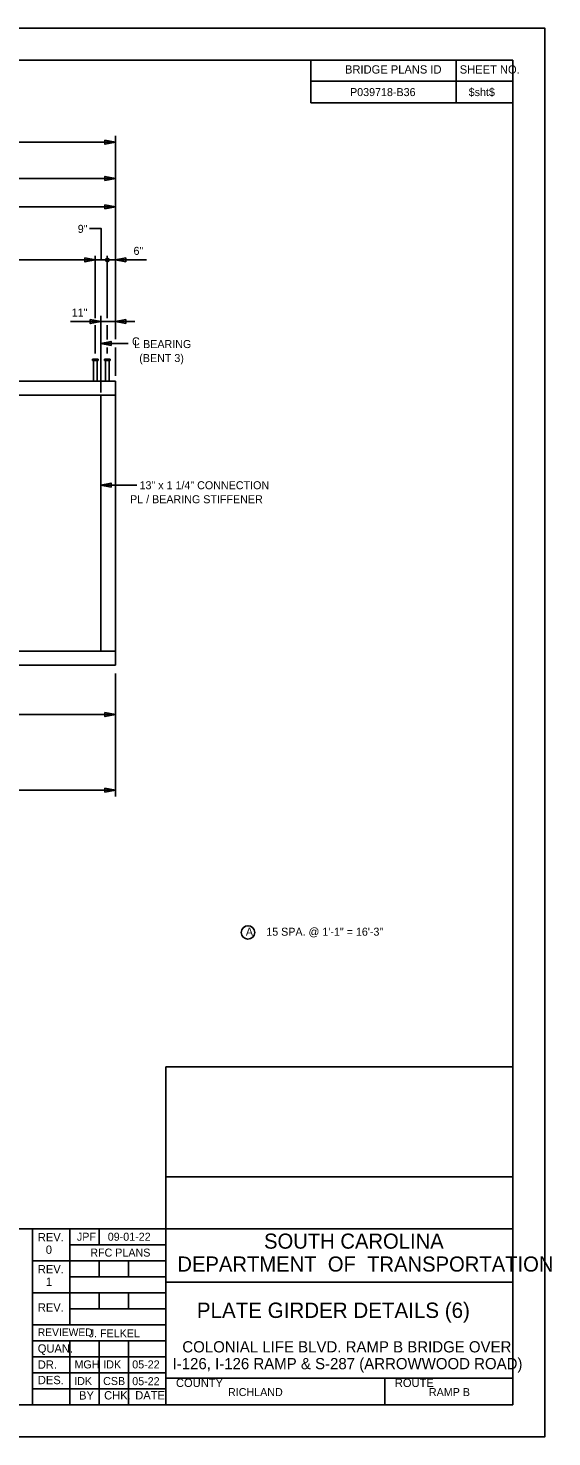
# Model space of a CAD drawing. Extents: x -305 to -161, y -187 to -99.
# Drawn here: x -193.4 to -160.8, y -187.5 to -99.5 of the extents above; entities that cross this region are included whole.
import ezdxf

# ---------------------------------------------------------------- set-up
doc = ezdxf.new("R2010")
doc.units = 0
for name, color, linetype in [('BR_AUTO DIMENSION', 7, 'Continuous'), ('BR_BORDER LINES', 7, 'Continuous'), ('BR_CENTER LINES', 7, 'Continuous'), ('BR_STRUCTURAL STEEL', 7, 'Continuous'), ('BR_TEXT', 7, 'Continuous'), ('Default', 7, 'Continuous'), ('Level 31', 7, 'Continuous')]:
    doc.layers.add(name, color=color, linetype=linetype)

msp = doc.modelspace()

# ---------------------------------------------------------------- linework, layer by layer
at = {"layer": 'BR_AUTO DIMENSION'}
for p, q in [((-188.002, -118.927), (-188.002, -106.206)), ((-284.433, -106.618), (-188.002, -106.618)), ((-226.782, -108.876), (-188.002, -108.876)), ((-188.002, -110.653), (-206.782, -110.653)), ((-219.002, -113.971), (-189.252, -113.971)), ((-189.252, -117.609), (-189.252, -113.71)), ((-186.048, -113.971), (-189.252, -113.971)), ((-188.502, -117.609), (-188.502, -113.71)), ((-190.801, -117.821), (-186.779, -117.821)), ((-189.252, -119.81), (-189.252, -118.048)), ((-188.502, -118.929), (-188.502, -118.048)), ((-188.918, -119.183), (-187.195, -119.183)), ((-188.502, -119.81), (-188.502, -119.447)), ((-188.002, -121.218), (-188.002, -119.447)), ((-188.918, -128.037), (-186.655, -128.037)), ((-188.002, -139.795), (-188.002, -147.486)), ((-188.002, -142.367), (-213.532, -142.367)), ((-206.782, -147.085), (-188.002, -147.085))]:
    msp.add_line(p, q, dxfattribs=at)
for points in [[(-188.652, -106.493), (-188.002, -106.618), (-188.652, -106.743)], [(-188.652, -109.001), (-188.002, -108.876), (-188.652, -108.751)], [(-188.652, -110.778), (-188.002, -110.653), (-188.652, -110.528)], [(-189.902, -113.846), (-189.252, -113.971), (-189.902, -114.096)], [(-187.352, -114.096), (-188.002, -113.971), (-187.352, -113.846)], [(-189.568, -117.696), (-188.918, -117.821), (-189.568, -117.946)], [(-187.352, -117.946), (-188.002, -117.821), (-187.352, -117.696)], [(-188.268, -119.308), (-188.918, -119.183), (-188.268, -119.058)], [(-188.268, -128.162), (-188.918, -128.037), (-188.268, -127.912)], [(-188.652, -142.242), (-188.002, -142.367), (-188.652, -142.492)], [(-188.652, -146.96), (-188.002, -147.085), (-188.652, -147.21)]]:
    msp.add_lwpolyline(points, close=True, dxfattribs=at)
msp.add_lwpolyline([(-188.877, -113.971), (-188.877, -112.006), (-189.617, -112.006)], dxfattribs=at)
for centre, radius in [((-188.502, -113.971), 0.111), ((-179.72, -155.982), 0.417)]:
    msp.add_circle(centre, radius, dxfattribs=at)
at = {"layer": 'BR_BORDER LINES'}
for p, q in [((-163.178, -101.489), (-297.843, -101.489)), ((-175.788, -104.156), (-175.788, -101.489)), ((-166.722, -104.156), (-166.722, -101.489)), ((-163.178, -185.489), (-163.178, -101.489)), ((-175.788, -102.808), (-163.178, -102.808)), ((-166.722, -102.808), (-163.178, -102.808)), ((-163.178, -104.156), (-175.788, -104.156)), ((-184.846, -185.489), (-184.846, -164.383)), ((-184.846, -164.383), (-163.178, -164.383)), ((-184.845, -171.242), (-163.178, -171.242)), ((-214.64, -174.489), (-193.18, -174.489)), ((-193.18, -185.489), (-193.18, -174.489)), ((-193.18, -174.489), (-163.178, -174.489)), ((-190.846, -174.489), (-190.846, -180.489)), ((-189.013, -175.489), (-189.013, -174.489)), ((-190.846, -175.489), (-184.846, -175.489)), ((-193.18, -176.489), (-184.846, -176.489)), ((-189.013, -177.489), (-189.013, -176.489)), ((-187.179, -177.489), (-187.179, -176.489)), ((-190.846, -177.489), (-184.846, -177.489)), ((-193.18, -178.489), (-184.846, -178.489)), ((-189.013, -179.489), (-189.013, -178.489)), ((-187.179, -179.489), (-187.179, -178.489)), ((-184.846, -177.822), (-184.846, -177.822)), ((-184.846, -177.823), (-163.178, -177.823)), ((-190.846, -179.489), (-184.846, -179.489)), ((-193.18, -180.489), (-184.846, -180.489)), ((-193.18, -181.489), (-184.846, -181.489)), ((-190.846, -181.489), (-190.846, -185.489)), ((-189.013, -181.489), (-189.013, -185.489)), ((-187.179, -181.489), (-187.179, -185.489)), ((-193.18, -182.489), (-184.846, -182.489)), ((-193.18, -183.489), (-184.846, -183.489)), ((-184.846, -183.823), (-163.178, -183.823)), ((-184.456, -183.823), (-163.178, -183.823)), ((-171.179, -185.489), (-171.179, -183.823)), ((-193.18, -184.489), (-184.846, -184.489)), ((-297.843, -185.489), (-163.178, -185.489))]:
    msp.add_line(p, q, dxfattribs=at)
at = {"layer": 'BR_CENTER LINES'}
msp.add_line((-188.918, -117.463), (-188.918, -122.256), dxfattribs=at)
at = {"layer": 'BR_STRUCTURAL STEEL'}
for p, q in [((-188.002, -121.537), (-206.782, -121.537)), ((-188.002, -121.537), (-188.002, -122.412)), ((-188.002, -122.412), (-284.433, -122.412)), ((-188.918, -122.412), (-188.918, -138.412)), ((-188.002, -122.412), (-188.002, -138.412)), ((-188.002, -138.412), (-284.433, -138.412)), ((-188.002, -139.287), (-188.002, -138.412)), ((-188.002, -139.287), (-206.782, -139.287))]:
    msp.add_line(p, q, dxfattribs=at)
at = {"layer": 'Default'}
for p, q in [((-189.423, -120.162), (-189.423, -120.256)), ((-189.423, -120.162), (-189.08, -120.162)), ((-189.423, -120.256), (-189.08, -120.256)), ((-189.361, -120.256), (-189.361, -121.537)), ((-189.142, -120.256), (-189.142, -121.537)), ((-189.08, -120.162), (-189.08, -120.256)), ((-188.673, -120.162), (-188.673, -120.256)), ((-188.673, -120.162), (-188.33, -120.162)), ((-188.673, -120.256), (-188.33, -120.256)), ((-188.611, -120.256), (-188.611, -121.537)), ((-188.392, -120.256), (-188.392, -121.537)), ((-188.33, -120.162), (-188.33, -120.256))]:
    msp.add_line(p, q, dxfattribs=at)
at = {"layer": 'Level 31'}
msp.add_line((-174.011, -179.583), (-174.011, -179.583), dxfattribs=at)
msp.add_lwpolyline([(-305.176, -187.489), (-161.176, -187.489), (-161.176, -99.489), (-305.176, -99.489)], close=True, dxfattribs=at)

# ---------------------------------------------------------------- texts
at = {"layer": 'BR_AUTO DIMENSION'}
for s, p in [('9"', (-190.349, -112.275)), ('6"', (-186.867, -113.652)), ('11"', (-190.724, -117.502)), ('A', (-179.854, -156.185)), ('15 SPA. @ 1\'-1" = 16\'-3"', (-178.579, -156.185))]:
    msp.add_text(s, height=0.5, rotation=360, dxfattribs=at).set_placement(p)
at = {"layer": 'BR_TEXT'}
for s, height, p in [('BRIDGE PLANS ID', 0.52, (-173.663, -102.327)), ('SHEET NO.', 0.52, (-166.499, -102.327)), ('P039718-B36', 0.5, (-173.348, -103.732)), ('$sht$', 0.5, (-165.939, -103.732)), ('C', 0.5, (-186.962, -119.306)), ('L BEARING', 0.5, (-186.827, -119.473)), ('(BENT 3)', 0.5, (-186.509, -120.348)), ('13" x 1 1/4" CONNECTION ', 0.5, (-186.491, -128.293)), ('PL / BEARING STIFFENER', 0.5, (-187.083, -129.168)), ('REV.', 0.52, (-192.841, -175.277)), ('JPF', 0.5, (-190.4, -175.239)), ('09-01-22', 0.5, (-188.475, -175.239)), ('SOUTH CAROLINA', 0.94348, (-178.718, -175.735)), ('0', 0.52, (-192.345, -176.057)), ('RFC PLANS', 0.5, (-189.566, -176.229)), ('REV.', 0.52, (-192.841, -177.277)), ('DEPARTMENT  OF  TRANSPORTATION', 0.94348, (-184.129, -177.166)), ('1', 0.52, (-192.337, -178.057)), ('REV.', 0.52, (-192.841, -179.667)), ('PLATE GIRDER DETAILS (6)', 0.96, (-182.913, -180.063)), ('REVIEWED', 0.48, (-192.843, -181.195)), ('J. FELKEL', 0.5, (-189.664, -181.272)), ('QUAN.', 0.52, (-192.846, -182.229)), ('COLONIAL LIFE BLVD. RAMP B BRIDGE OVER', 0.7, (-183.82, -182.216)), ('DR.', 0.52, (-192.845, -183.235)), ('MGH', 0.5, (-190.552, -183.215)), ('IDK', 0.5, (-188.755, -183.215)), ('05-22', 0.5, (-186.948, -183.215)), ('I-126, I-126 RAMP & S-287 (ARROWWOOD ROAD) ', 0.7, (-184.429, -183.266)), ('DES.', 0.52, (-192.841, -184.2)), ('IDK', 0.5, (-190.57, -184.254)), ('CSB', 0.5, (-188.764, -184.254)), ('05-22', 0.5, (-186.948, -184.263)), ('COUNTY', 0.52, (-184.217, -184.376)), ('ROUTE', 0.52, (-170.55, -184.376)), ('BY', 0.52, (-190.265, -185.161)), ('CHK.', 0.52, (-188.701, -185.156)), ('DATE', 0.52, (-186.761, -185.156)), ('RICHLAND', 0.5, (-180.968, -184.944)), ('RAMP B', 0.5, (-168.424, -184.944))]:
    msp.add_text(s, height=height, dxfattribs=at).set_placement(p)

doc.saveas('drawing.dxf')
